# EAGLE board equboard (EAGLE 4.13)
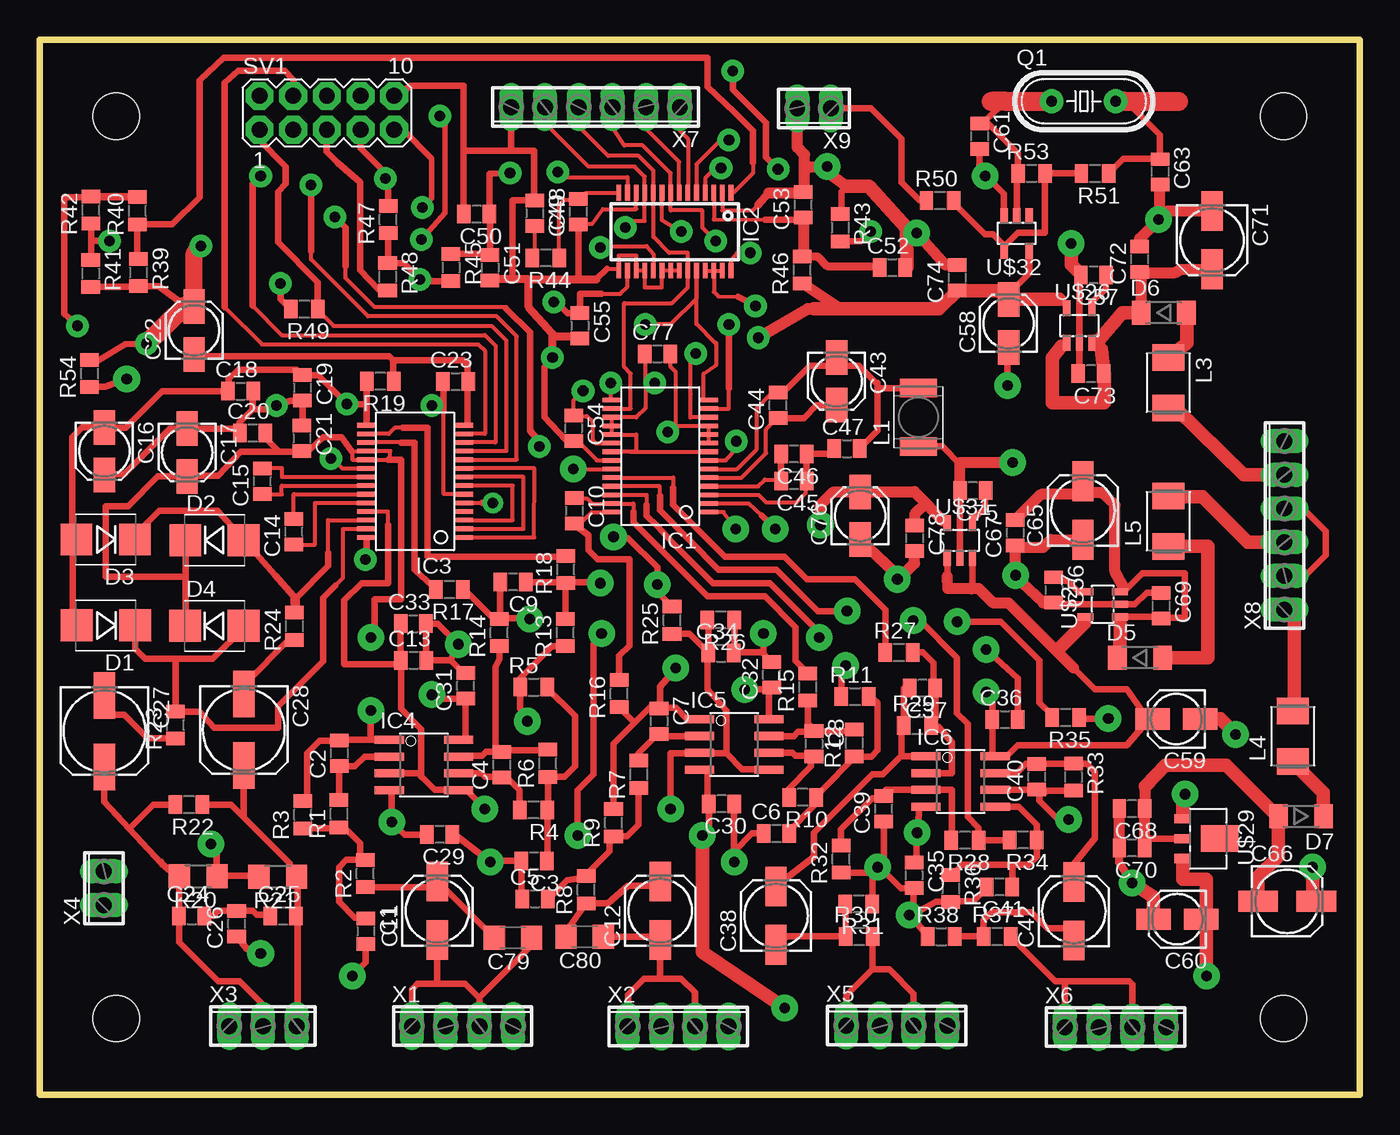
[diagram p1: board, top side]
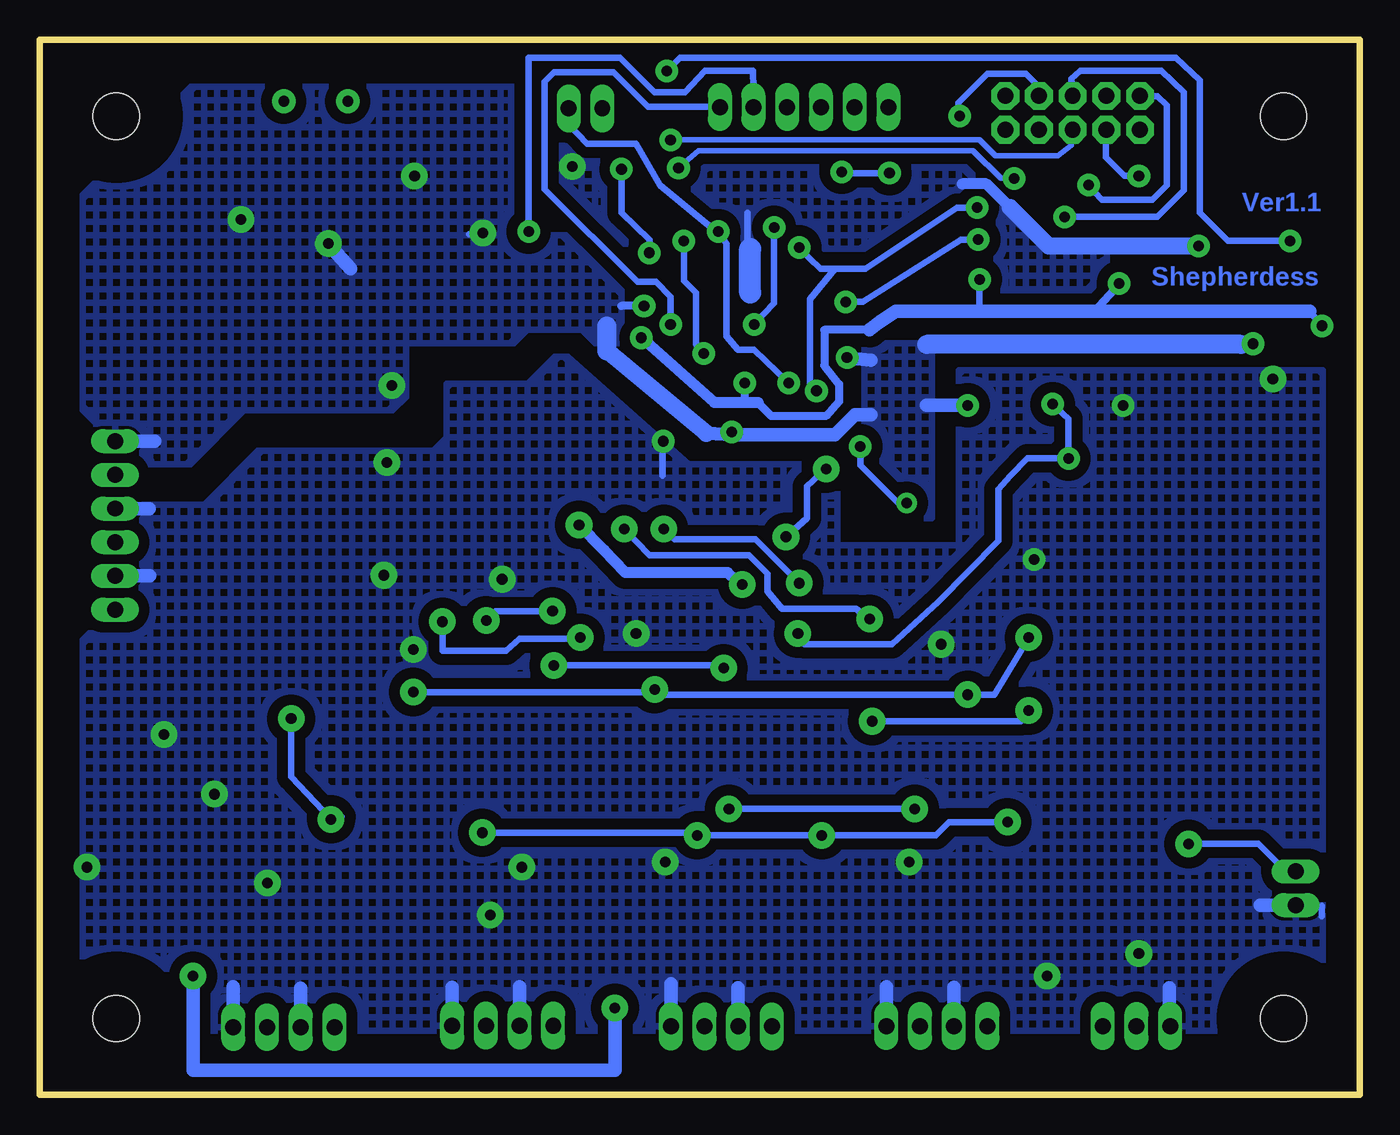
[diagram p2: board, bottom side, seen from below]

Size 99.5 x 79.5 mm. Coordinates in mm from the lower left corner, seen from the top.
Outline: 0,0 0,79.5 99.5,79.5 99.5,0 0,0
Copper layers (1*16): Top 0.035mm / dielectric 1.5mm / Bottom 0.035mm
Design rules "default": minimum track width 10mil, minimum drill 30mil, track to track 12mil, track to pad 12mil, pad to pad 10mil, via to via 10mil, smd to smd 8mil, copper to edge 20mil, drill to drill 20mil, minimum pad ring 10mil, minimum via ring 8mil, stop-mask expansion 4mil, vias tented up to drill 40mil, thermal gap 10mil
Net classes: 1 Phantom: drill 0.711 mm
Holes 3.5 mm at 93.75,5.75 5.75,5.75 5.75,73.75 93.75,73.75
bRestrict: area 3.4,3.4 to 8.1,8.1; area 91.5,3.5 to 96,8.1; area 91.5,71.5 to 96,76; area 3.5,71.5 to 8.1,76

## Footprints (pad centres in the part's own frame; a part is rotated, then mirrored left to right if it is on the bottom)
C0805 = smd 1.016 x 1.397: 1 -0.96,0; 2 0.96,0
153CLV-0505 = smd 3 x 1.6: + 2.2,0; - -2.2,0
153CLV-0405 = smd 2.6 x 1.6: + 1.8,0; - -1.8,0
153CLV-0605 = smd 3.5 x 1.6: + 2.7,0; - -2.7,0
C1206 = smd 1.6 x 1.8: 1 -1.4,0; 2 1.4,0
SMB = smd 2.4 x 2.4: 1 -2.2,0; 2 2.2,0
SOD80 = smd 1.4 x 1.8: 1 -1.7,0; 2 1.7,0
SSOP28DB = smd 0.348 x 1.397: 1 -4.225,-3.656; 2 -3.575,-3.656; 3 -2.925,-3.656; 4 -2.275,-3.656; 5 -1.625,-3.656; 6 -0.975,-3.656; 7 -0.325,-3.656; 8 0.325,-3.656; 9 0.975,-3.656; 10 1.625,-3.656; 11 2.275,-3.656; 12 2.925,-3.656; 13 3.575,-3.656; 14 4.225,-3.656; 15 4.225,3.656; 16 3.575,3.656; 17 2.925,3.656; 18 2.275,3.656; 19 1.625,3.656; 20 0.975,3.656; 21 0.325,3.656; 22 -0.325,3.656; 23 -0.975,3.656; 24 -1.625,3.656; 25 -2.275,3.656; 26 -2.925,3.656; 27 -3.575,3.656; 28 -4.225,3.656
PSO28 = smd 0.35 x 1.2: 1 -4.225,-2.925; 2 -3.575,-2.925; 3 -2.925,-2.925; 4 -2.275,-2.925; 5 -1.625,-2.925; 6 -0.975,-2.925; 7 -0.325,-2.925; 8 0.325,-2.925; 9 0.975,-2.925; 10 1.625,-2.925; 11 2.275,-2.925; 12 2.925,-2.925; 13 3.575,-2.925; 14 4.225,-2.925; 15 4.225,2.925; 16 3.575,2.925; 17 2.925,2.925; 18 2.275,2.925; 19 1.625,2.925; 20 0.975,2.925; 21 0.325,2.925; 22 -0.325,2.925; 23 -0.975,2.925; 24 -1.625,2.925; 25 -2.275,2.925; 26 -2.925,2.925; 27 -3.575,2.925; 28 -4.225,2.925
SO08 = smd 0.61 x 2.21: 1 -1.905,-2.616; 2 -0.635,-2.616; 3 0.635,-2.616; 4 1.905,-2.616; 5 1.905,2.616; 6 0.635,2.616; 7 -0.635,2.616; 8 -1.905,2.616
L5038P = smd 1.4 x 2.8: 1 -2.2,0; 2 2.2,0
L4532M = smd 2 x 2.4: 1 -1.9,0; 2 1.9,0
HC49/S = drill 0.8 pad 1.778 round: 1 -2.413,0; 2 2.413,0
R0805 = smd 1.016 x 1.397: 1 -1.023,0; 2 1.023,0
R1206 = smd 1.6 x 1.803: 1 -1.422,0; 2 1.422,0
MA05-2 = drill 1.2 pad 2.1 octagon: 1 -5.08,-1.27; 2 -5.08,1.27; 3 -2.54,-1.27; 4 -2.54,1.27; 5 0,-1.27; 6 0,1.27; 7 2.54,-1.27; 8 2.54,1.27; 9 5.08,-1.27; 10 5.08,1.27
SOT23-5 = smd 0.55 x 1.2: 1 -0.95,-1.3; 2 0,-1.3; 3 0.95,-1.3; 4 0.95,1.3; 5 -0.95,1.3
SOT89R = smd 0.7 x 1.1: 1 -1.5,-1.75; 2 0,-1.75; 3 1.5,-1.75 | smd 2 x 2.8: 4 0,1.1
4POL254 = drill 1.2 long: 1 -3.81,0; 2 -1.27,0; 3 1.27,0; 4 3.81,0
3POL254 = drill 1.2 long: 1 -2.54,0; 2 0,0; 3 2.54,0
2POL254 = drill 1.2 long: 1 -1.27,0; 2 1.27,0
6POL254 = drill 1.2 pad 1.778 long: 1 -6.35,0; 2 -3.81,0; 3 -1.27,0; 4 1.27,0; 5 3.81,0; 6 6.35,0

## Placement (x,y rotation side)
C1  1n  [C0805]  24.58,12.32 270 top
C2  220p  [C0805]  22.59,25.73 90 top
C3  1n  [C0805]  37.27,17.62 180 top
C4  220p  [C0805]  34.84,24.88 90 top
C5  1n  [C0805]  37.35,14.77 0 top
C6  1n  [C0805]  55.55,19.7 0 top
C7  220p  [C0805]  46.68,28.15 270 top
C8  220p  [C0805]  58.36,26.45 270 top
C9  220p  [C0805]  35.67,38.64 180 top
C10  220p  [C0805]  40.29,44.02 270 top
C11  47u 10V  [153CLV-0505]  29.97,13.87 90 top
C12  47u 10V  [153CLV-0505]  46.77,13.87 90 top
C13  100n (X7R)  [C0805]  28.18,32.74 0 top
C14  1u  [C0805]  19.16,42.43 90 top
C15  1u  [C0805]  16.78,46.23 90 top
C16  10u 6V  [153CLV-0405]  4.87,48.5 270 top
C17  10u 6V  [153CLV-0405]  11.11,48.4 270 top
C18  100n  [C0805]  15.13,53.02 0 top
C19  100n  [C0805]  19.8,53.27 270 top
C20  100n  [C0805]  16.03,49.88 0 top
C21  100n  [C0805]  19.76,49.47 270 top
C22  10u 6V  [153CLV-0405]  11.63,57.6 90 top
C23  100n  [C0805]  31.33,53.75 0 top
C24  1n  [C0805]  11.46,13.49 0 top
C25  1n  [C0805]  18.34,13.48 0 top
C26  1n  [C0805]  14.84,12.9 90 top
C27  33u 63V  [153CLV-0605]  4.88,27.4 270 top
C28  33u 63V  [153CLV-0605]  15.38,27.5 270 top
C29  10n  [C0805]  30.14,19.61 180 top
C30  10n  [C0805]  51.39,21.93 180 top
C31  10n  [C0805]  32.1,30.81 90 top
C32  10n  [C0805]  55.17,31.66 90 top
C33  2.2u  [C0805]  28.16,35.5 0 top
C34  2.2u  [C0805]  51.36,33.28 0 top
C35  100n  [C0805]  65.9,16.54 270 top
C36  100n  [C0805]  72.76,28.28 0 top
C37  33p  [C0805]  66.54,30.64 180 top
C38  47u 10V  [153CLV-0505]  55.5,13.5 90 top
C39  33p  [C0805]  63.62,21.56 90 top
C40  33p  [C0805]  75.16,23.96 90 top
C41  33p  [C0805]  72.34,15.66 180 top
C42  47u 10V  [153CLV-0505]  77.95,13.83 90 top
C43  15u  [153CLV-0405]  60.07,53.77 270 top
C44  100n  [C0805]  55.65,51.96 90 top
C45  100n  [C0805]  56.84,46.27 180 top
C46  1u  [C0805]  56.84,48.29 180 top
C47  100n  [C0805]  60.86,48.69 0 top
C48  68n  [C0805]  37.32,66.44 270 top
C49  1.5n  [C0805]  40.6,66.56 90 top
C50  100n  [C0805]  32.94,66.36 180 top
C51  2.2u  [C0805]  33.94,62.34 270 top
C52  2.2u  [C0805]  64.26,62.34 0 top
C53  100n  [C0805]  57.55,67.06 90 top
C54  10n  [C0805]  40.24,50.24 270 top
C55  10n  [C0805]  40.72,57.94 270 top
C56  10n (X7R)  [C0805]  76.44,38.04 270 top
C57  10n (X7R)  [C0805]  79.44,61.78 180 top
C58  15u (low ESR)  [153CLV-0405]  73.03,58.13 90 top
C59  10u (low ESR)  [153CLV-0405]  85.67,28.32 180 top
C60  10u (low ESR)  [153CLV-0405]  85.76,13.23 180 top
C61  18p  [C0805]  70.84,72.24 270 top
C63  18p  [C0805]  84.44,69.54 270 top
C65  22u 16V  [153CLV-0505]  78.63,44.03 90 top
C66  22u 16V  [153CLV-0505]  94.03,14.58 0 top
C67  1u  [C0805]  73.54,42.36 90 top
C68  1u  [C0805]  82.34,21.56 180 top
C69  100n (X7R)  [C0805]  84.52,36.84 270 top
C70  100n (X7R)  [C0805]  82.34,18.6 180 top
C71  22u 16V  [153CLV-0505]  88.37,64.4 270 top
C72  1u  [C0805]  82.92,62.96 90 top
C73  100n  [C0805]  79.24,54.34 180 top
C74  100n  [C0805]  69.16,61.56 90 top
C75  10n (X7R)  [C0805]  70.34,45.52 180 top
C76  10u (low ESR)  [153CLV-0405]  61.84,43.63 90 top
C77  100n  [C0805]  46.56,55.84 0 top
C78  100n  [C0805]  65.94,41.94 270 top
C79  4.7u  [C1206]  35.67,11.83 180 top
C80  4.7u  [C1206]  41.07,11.92 180 top
D1  [SMB]  4.98,35.38 180 top
D2  [SMB]  13.18,41.79 0 top
D3  [SMB]  4.97,41.85 180 top
D4  MBRA120LT3  [SMB]  13.17,35.34 0 top
D5  BAT42  [SOD80]  82.93,32.94 0 top
D6  BAT42  [SOD80]  84.73,58.92 0 top
D7  BAT42  [SOD80]  95.07,21 180 top
IC1  TLC320AD77  [SSOP28DB]  46.77,48.13 90 top
IC2  TAS3001  [PSO28]  47.88,65.04 180 top
IC3  PGA2500  [SSOP28DB]  28.29,46.23 90 top
IC4  OPA2134U  [SO08]  28.96,24.85 270 top
IC5  OPA2134U  [SO08]  52.35,26.4 270 top
IC6  OPA2134U  [SO08]  69.41,23.61 270 top
L1  33 uH  [L5038P]  66.23,51.06 90 top
L3  22uH 185mA  [L4532M]  85.07,53.67 270 top
L4  22uH 185mA  [L4532M]  94.45,27.03 90 top
L5  22uH 185mA  [L4532M]  85.07,43.23 90 top
Q1  24.576 MHz  [HC49/S]  78.7,74.87 0 top
R1  12k  [R0805]  22.56,21.18 90 top
R2  5.6k  [R0805]  24.53,16.68 90 top
R3  5.6k  [R0805]  19.82,21.1 90 top
R4  12k  [R0805]  37.22,21.46 180 top
R5  5.6k  [R0805]  37.23,30.72 0 top
R6  5.6k  [R0805]  38.3,24.98 90 top
R7  12k  [R0805]  45.16,24.15 90 top
R8  5.6k  [R0805]  41.18,15.45 90 top
R9  5.6k  [R0805]  43.25,20.5 90 top
R10  12k  [R0805]  57.5,22.42 180 top
R11  5.6k  [R0805]  61.45,30.01 0 top
R12  5.6k  [R0805]  61.41,26.5 90 top
R13  1k  [R0805]  39.61,34.83 90 top
R14  1k  [R0805]  34.63,34.83 90 top
R15  1k  [R0805]  57.9,30.73 90 top
R16  1k  [R0805]  43.67,30.23 90 top
R17  1k  [R0805]  30.88,38.07 180 top
R18  1k  [R0805]  39.65,39.58 90 top
R19  10  [R0805]  25.67,53.77 180 top
R20  6.81k  [R1206]  11.94,16.47 180 top
R21  6.81k  [R1206]  17.94,16.44 180 top
R22  620  [R0805]  11.24,21.86 180 top
R23  0 - 100  [R0805]  10.23,27.86 90 top
R24  0 - 100  [R0805]  19.2,35.31 90 top
R25  4.7k  [R0805]  47.66,35.76 90 top
R26  4.7k  [R0805]  51.34,35.78 180 top
R27  10k  [R0805]  64.76,33.34 0 top
R28  10k  [R0805]  69.74,19.18 180 top
R29  10k  [R0805]  66.16,27.84 0 top
R30  220  [R0805]  61.76,11.94 0 top
R31  100k  [R0805]  61.74,14.38 180 top
R32  100k  [R0805]  60.4,17.76 90 top
R33  10k  [R0805]  77.92,23.94 270 top
R34  10k  [R0805]  74.14,19.2 180 top
R35  10k  [R0805]  77.34,28.42 180 top
R36  100k  [R0805]  68.66,15.54 270 top
R37  220  [R0805]  72.16,11.94 0 top
R38  100k  [R0805]  67.96,11.92 0 top
R39  0  [R0805]  7.44,61.96 270 top
R40  inf  [R0805]  7.36,66.62 90 top
R41  0  [R0805]  3.84,61.9 270 top
R42  inf  [R0805]  3.86,66.68 90 top
R43  100k  [R0805]  60.34,65.34 270 top
R44  27  [R0805]  38.14,63.06 180 top
R45  2.7  [R0805]  31,62.34 270 top
R46  2.7  [R0805]  57.47,62.16 90 top
R47  5k(1board)  [R0805]  26.26,65.96 90 top
R48  5k(1board)  [R0805]  26.22,61.64 270 top
R49  10k  [R0805]  19.94,59.2 180 top
R50  100  [R0805]  67.86,67.4 0 top
R51  240  [R0805]  79.54,69.42 180 top
R53  750k  [R0805]  74.76,69.44 0 top
R54  10  [R0805]  3.76,54.36 90 top
SV1  [MA05-2]  21.64,74 0 top
U$26  LP2985IM5-3.3  [SOT23-5]  78.36,57.97 0 top
U$27  LP2985IM5-5.0  [SOT23-5]  80.13,36.96 90 top
U$29  79L05  [SOT89R]  87.83,19.3 270 top
U$31  LP2985IM5-3.3  [SOT23-5]  69.36,41.77 0 top
U$32  SN74AHC1G14  [SOT23-5]  73.64,64.92 180 top
X1  [4POL254]  31.87,5.17 0 top
X2  [4POL254]  48.12,5.15 0 top
X3  [3POL254]  16.83,5.17 0 top
X4  [2POL254]  4.83,15.56 90 top
X5  [4POL254]  64.6,5.21 0 top
X6  [4POL254]  81.1,5.09 0 top
X7  [6POL254]  41.89,74.43 180 top
X8  [6POL254]  93.83,42.91 90 top
X9  [2POL254]  58.37,74.33 180 top

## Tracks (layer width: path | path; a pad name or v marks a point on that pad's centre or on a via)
+3V3  (via drill 0.8 pad 2)
  Top 0.305: IC1.23 40.74,47.16 v40.23,47.17
  Top 0.508: R25.2 46.75,37.69 v46.55,38.45 46.55,39.75 44.35,41.95 v43.25,42.05 | U$31.5 68.41,43.09 68.25,43.15 68.05,43.25 | v58.85,42.95 58.85,43.05 | C76.+ 61.84,45.36 61.85,45.35 61.85,45.45
  Top 0.813: 66.78,44.58 65.95,45.45 61.85,45.45 | 66.78,44.58 68.05,43.25 | 66.78,44.58 65.94,43.74 C78.1 | C76.+ 59.83,45.43 58.85,44.45 58.85,43.05
  Bottom 0.508: v58.85,42.95 58.37,42.57 | v40.23,47.17 41.65,45.85 41.65,43.45 v43.25,42.05
  Bottom 0.813: v46.55,38.45 47.65,39.35 55.35,39.35 56.95,41.05 v58.85,42.95
+5V  (via drill 0.8 pad 2)
  Top 0.305: 26.25,47.85 IC3.19 23.55,47.85 23.55,48.51 | 23.5,48.51 23.55,48.51 | 23.55,48.51 IC3.18 | C21.2 19.76,48.54 19.75,48.55 20.25,48.55 | 24.88,48.51 26.42,48.51 26.42,47.84
  Top 0.508: D4.1 10.99,36.24 11,36.25 10.98,36.37 10.98,39.05 | 10.98,39.05 D2.1 | 31.25,26.75 IC4.8 31.55,26.75 32.15,26.75 32.1,26.8 C31.1 29.85,29.85 v29.55,30.15 | v53.15,30.55 54.95,30.55 55.15,30.75 | 55.15,30.75 55.17,30.73 C32.1 | IC5.8 54.97,30.57 55.15,30.75 | v71.35,30.35 71.8,30.3 C36.1 71.8,25.6 71.75,25.55 71.78,25.52 IC6.8 72.92,25.52 73.75,26.35 81.95,26.35 83.27,27.87 C59.+ 83.38,28.52 81.95,30.55 79.55,30.55 77.95,32.15 | v24.95,34.45 25.25,35.05 25.25,37.35 27.25,37.35 27.25,47.85 26.25,47.85 26.25,47.84 26.42,47.84 | 23.5,48.51 22.75,49.55 21.35,49.55 20.25,48.55 | 19.75,48.55 19.65,48.55 19.45,48.45 18.05,48.45 | 18.05,48.45 15.15,48.45 13.45,46.65 11.15,46.65 C17.+ 8.9,46.6 6.65,44.35 4.97,44.35 4.97,39.05 10.98,39.05 | C20.2 16.99,49.51 18.05,48.45 | U$27.5 78.79,36.05 78.75,36.05 78.75,35.55 | 76.65,33.45 76.85,33.65 | U$31.3 70.32,40.15 70.32,40.17 70.32,40.05 | 68.41,39.04 U$31.1 | 70.32,40.05 70.28,40.05 | 70.31,38.15 70.31,40.05 70.32,40.05
  Top 0.813: 77.95,32.15 76.65,33.45 73.05,37.05 71.89,37.05 70.79,38.15 70.15,38.15 | 68.41,39.04 68.44,38.15 70.15,38.15 | 70.15,38.15 70.31,38.15
  Top 1: 76.85,33.65 78.75,35.55
  Bottom 0.508: v71.35,30.35 53.35,30.35 v53.15,30.55 52.35,30.15 v29.55,30.15 27.55,30.15 v24.95,34.45
-5V  (via drill 0.8 pad 1.7, 0.8 pad 2)
  Top 0.305: IC3.20 22.8,47.2 22.05,47.95 v21.95,47.95 | IC3.15 24.65,50.45 24.65,50.75
  Top 0.508: 2.47,36.03 2.38,36.12 D1.2 | 2.47,36.03 2.47,41.75 | 2.47,41.75 D3.2 | 2.47,36.03 2.5,36 | IC4.4 26.45,22.95 26.52,22.88 26.52,20.58 v26.55,20.55 27.49,19.61 C29.2 | v40.55,19.55 40.55,22.95 41.75,24.15 41.75,33.95 v42.35,34.75 | IC5.4 49.79,24.55 50.35,24.55 50.35,21.95 50.41,21.95 C30.2 50.43,20.03 v49.95,19.55 | IC6.4 66.31,21.7 v66.15,19.75 66.1,19.4 66.1,18 66.15,17.95 C35.1 | U$29.3 86.08,17.82 86.15,17.35 | 24.65,52.05 v23.15,52.05 20.97,54.23 C19.1 19.38,54.65 14.95,54.65 14.25,53.95 14.25,52.95 C18.1 9.22,53.02 6.47,50.27 | 24.65,52.05 24.65,50.75 | R19.2 24.65,52.05 | 6.47,50.27 4.75,50.15 | 6.47,50.27 C16.- 3.2,50.3 2.45,49.55 2.45,41.75 2.47,41.75
  Top 1: v49.95,19.55 49.95,10.75 v56.15,6.55 | C60.- 87.56,13.56 87.55,13.55 87.75,13.35 | v87.95,8.95 87.95,13.15 87.75,13.35 | 86.15,17.35 86.15,16.25 87.95,16.25 87.95,13.55 87.75,13.35
  Bottom 0.508: v26.55,20.55 30.95,20.55 31.95,19.55 v40.55,19.55 v49.95,19.55 50.75,19.75 v66.15,19.75 | v42.35,34.75 41.85,33.95 35.25,33.95 31.75,37.15 27.25,41.75 27.25,45.65 26.35,46.65 25.05,47.95 v21.95,47.95 21.95,50.95 v23.15,52.05 23.15,52.15 23.25,52.05
  Bottom 1: v56.15,6.55 56.15,1.85 87.95,1.85 v87.95,8.95
AGND  (via drill 0.8 pad 1.7, 0.8 pad 2)
  Top 0.305: 24.6,42.01 IC3.28 24.65,41.8 | IC1.7 51.7,47.8 52.5,48.65 v52.5,49.25
  Top 0.406: 14.25,5.25 14.29,5.21 X3.1
  Top 0.508: C1.2 24.58,9.98 v23.55,8.95 | C29.1 31.29,19.61 v33.95,17.55 33.88,17.62 C3.2 36.31,14.59 36.35,14.55 36.39,14.59 C5.1 | 31.95,31.75 31.97,31.77 C31.2 | C13.2 30.96,32.74 31.95,31.75 | 31.95,31.75 30.95,32.75 v31.55,33.95 30,35.5 C33.2 29.12,32.78 C13.2 | C26.1 15.64,10.96 v16.65,10.65 | C30.1 52.35,18.55 52.25,18.44 | v52.35,17.55 52.25,18.44 | 52.25,18.44 52.26,18.44 52.35,18.35 53.7,19.7 C6.1 | C13.2 | C36.2 73.72,31.38 v71.35,33.55 | C70.2 81.38,18.58 81.35,18.55 | U$29.1 86.08,20.88 86.15,21.15 | C39.1 63.62,17.55 v63.15,17.15 | R32.1 63.16,16.74 | R31.1 62.76,16.36 v63.15,17.15 | 63.16,16.74 v63.15,17.15 | 63.16,16.74 63.16,16.96 63.35,17.15 64.92,15.58 C35.2 65.92,15.58 65.85,15.35 65.85,14.55 v65.55,13.55 | C41.2 71.38,15.58 70.38,14.58 68.78,14.58 68.72,14.72 R36.2 68.63,14.55 67.55,14.55 66.45,13.95 v65.55,13.55 | R38.1 66.94,11.96 65.85,13.25 v65.55,13.55 | v24.55,40.35 24.63,40.87 24.65,40.87 24.65,41.8 | 19.76,50.36 19.75,50.35 | 19.76,50.36 C21.1 | 19.76,50.36 19.8,50.4 C19.2 18.91,52.31 v17.85,51.95 17.55,51.65 16.05,51.65 | 16.05,51.65 15.07,50.67 C20.1 15.12,49.88 | C18.2 16.05,52.98 16.05,51.65 | 15.12,49.88 15.15,49.85 | 15.12,49.88 14.8,50.2 C17.- 9.8,50.2 6.35,46.75 4.85,46.75 4.87,46.73 C16.+ | 52.32,33.15 52.25,33.15 | C34.2 52.32,33.15 | 52.36,33.35 52.36,33.15 52.32,33.15 | 52.36,33.35 R26.1 | 52.36,33.35 52.25,33.35 | 54.44,33.35 C32.2 | 52.36,33.35 54.44,33.35 | 54.44,33.35 54.55,33.36 v54.55,34.75 | 64.85,38.95 v64.65,38.85 64.65,38.95 64.64,38.94 64.64,38.74 | C56.2 76.24,36.94 76.36,36.96 | 76.36,36.96 U$27.2 82.56,36.96 83.45,37.85 84.45,37.85 84.5,37.8 C69.1
  Top 0.508: 75.64,37.06 76.36,36.96 | v73.55,39.15 73.55,39.05 73.55,38.95 73.54,38.95 | 73.54,41.25 C67.1 | 73.54,38.94 73.45,38.85 | C75.2 69.38,45.78 69.35,45.75 69.36,45.74 U$31.2 | 69.38,47.45 69.45,47.45 68.04,48.86 L1.1 | X8.2 95.4,39.1 96.95,40.65 96.95,42.45 95.25,44.15 93.85,44.15 X8.4 | R54.1 4.94,53.34 v6.55,53.95
  Top 0.61: C70.2 81.38,17.52 v82.35,15.95
  Top 0.813: C70.2 C68.2 | 75.64,37.06 73.55,39.05 | 73.54,38.94 73.54,38.95 73.54,41.25 75.65,41.25 76.23,41.83 C65.- | C76.- 64.44,39.36 64.62,38.74 | 64.62,38.74 64.65,38.65 | C75.2 69.38,47.45 69.38,47.65 v73.35,47.65 | 64.62,38.74 64.64,38.74 65.94,40.04 C78.2
  Top 1: C60.+ 83.96,14.94 v82.35,15.95 | 86.15,21.15 86.15,21.95 86.35,22.45 v86.35,22.65 | C66.+ 95.95,15.1 v95.95,17.15 | C59.- 88.98,28.32 v90.15,27.15
  Bottom 0.508: 14.35,5.15 14.33,5.17 X3.1 | v33.95,17.55 33.75,17.55 | v64.65,38.85 64.65,38.95 64.75,38.95 | v52.5,49.25 52.55,49.25 52.55,46.65 | 2.85,13.45 2.85,14.25
  Bottom 1: 14.35,5.15 14.35,8.05 | 91.2,39.1 X8.2 | X6.4 84.91,8.15 | X6.2 79.83,8.03 | X5.4 68.41,8.09 | X5.2 63.33,5.33 63.35,5.45 63.35,8.15 | X2.4 51.93,8.35 | X2.2 46.85,8.05 | X1.2 30.6,8.1 | X1.4 35.68,8.15 | X4.1 7.51,14.29 | X8.4 93.85,44.16 93.85,44.15 91.25,44.15
  pour Bottom (isolate 0.813, hatched): 2.8,54.61 30.23,54.61 30.23,41.41 39.37,41.41 39.37,47.5 50.55,47.5 59.69,55.63 60.71,55.63 62.74,53.6 68.84,53.6 68.84,49.53 69.85,48.52 83.06,48.52 87.13,44.45 95.25,44.45 95.25,35.31 96.27,34.29 96.27,9.91 91.19,4.83 6.86,4.83 2.8,8.89
AUDMCLK  (via drill 0.8 pad 1.7)
  Top 0.305: IC2.9 46.91,65.91 v48.35,65.05 | IC1.15 43.05,52.42 v43.05,53.65
  Top 0.508: R50.1 66.3,67.4 64.95,68.75 64.95,72.05 62.65,74.35 60.05,74.35 59.97,74.43 | 59.97,74.43 59.95,74.45 | X9.1 59.97,74.43
  Bottom 0.305: 59.65,74.35 X9.1 59.65,74.35 | 59.65,74.35 59.75,74.35 | v48.35,65.05 48.85,65.35 | 59.65,73.15 59.65,74.35
  Bottom 0.508: v48.35,65.05 47.75,64.15 47.75,57.15 46.85,56.15 45.65,56.15 v43.05,53.65 | 48.85,65.35 52.75,68.55 54.55,71.65 58.25,71.65 59.65,73.15
GND  (via drill 0.8 pad 1.7, 0.8 pad 2)
  Top 0.305: IC3.6 30.45,45.26 30.45,51.55 | IC1.9 50.43,49.73 50.45,49.75 | IC1.22 41.99,47.8 40.45,49.35 40.25,49.35 C54.2 | 47.95,50.31 47.95,54.45 47.55,54.85 47.55,55.75 | IC2.12 44.95,66.75 42.45,66.75 41.65,65.65 40.55,65.65 | 40.55,65.65 | C49.1 40.55,65.65 | 43.66,62.25 IC2.15 | 43.66,62.25 43.66,63.25 44.95,63.25 IC2.17 44.95,62.15 | IC2.26 50.8,60.51 51.15,60.16 52.65,60.15 | 57.25,68.05 57.32,68.05 C53.2 57.55,67.97 | 42.75,62.25 43.66,62.25 | IC2.27 51.45,62.15 51.41,62.12 IC2.26 | 50.16,62.15 50.15,62.15 | IC2.25 50.16,62.15 | IC2.26 50.19,62.12 50.16,62.15 | 47.55,62.15 | IC2.22 48.2,62.15 47.55,62.15 | 47.55,62.15 IC2.21 | 47.55,62.15 46.91,62.15 IC2.20 46.91,60.85 45.6,60.85 IC2.18 45.6,62.15 44.95,62.15 | 44.95,62.15 | IC2.2 51.45,66.65 53.75,66.65 54.15,67.05 | 47.86,50.24 47.85,50.25 48.01,50.41 IC1.11 50.43,49.77 50.45,49.75 | 50.45,49.75 50.45,49.76 IC1.10
  Top 0.508: 30.45,52.05 30.45,53.45 30.37,53.53 C23.1 | 30.45,51.55 30.45,52.05 | 30.45,52.05 30.15,51.95 v29.55,51.95 | C73.2 78.26,54.34 78.25,54.35 78.36,54.46 U$26.2 78.36,61.56 78.48,61.68 C57.2 | 72.93,56.57 C58.- | v72.95,53.45 72.93,56.57 | 72.95,56.35 72.95,56.45 | 72.95,56.35 72.95,55.95 | 72.93,56.57 72.93,56.37 72.95,56.35 | 68.28,62.52 C74.2 | 47.55,55.75 47.52,55.78 C77.2 | 66.11,64.79 v66.11,64.94 65.35,65.34 | 52.65,60.15 v53.95,59.45 | C53.2 57.32,68.02 57.25,67.95 | 7.52,60.88 7.46,60.94 R39.2 8.96,60.94 10.95,59.45 | 7.52,60.88 R41.2 | 7.52,60.88 7.55,60.85 | 11.55,59.45 11.6,59.4 C22.+ 11.63,59.45 11.65,59.45 11.65,59.55 | 35.54,71.15 X7.6 | 35.54,71.15 37.25,71.15 37.25,67.55 37.35,67.45 37.32,67.42 C48.1 35.65,67.4 35.65,61.45 | C50.2 31.95,66.39 31.95,71.15 | 35.54,71.15 35.55,71.15 | 35.54,71.15 31.95,71.15 | 41.95,61.45 42.75,62.25 | 31.95,71.15 31.95,76.05 27.95,76.05 26.75,75.15 26.63,75.27 | 26.63,75.27 26.55,75.35 | 26.63,75.27 SV1.10 | 65.35,62.37 C52.2 | 34.15,61.45 34.15,61.38 C51.2 | 40.52,56.98 40.65,56.95 | 40.52,56.98 C55.2 | 40.35,57.15 40.52,56.98 | C49.1 40.6,61.5 40.55,61.45 | 40.25,49.35 39.65,49.35 38.05,51.05 38.05,54.85 v38.65,55.55 | 38.65,57.15 38.65,57.35 | 47.95,50.31 47.86,50.24 47.49,49.95 v47.35,49.95 | 60.44,66.36 60.45,66.35 | 60.44,66.36 R43.1 | 57.55,67.97 57.65,67.95 | 57.65,69.55 57.69,69.95 | 4.46,55.36 4.45,55.35 | R54.2 4.46,55.36 | v8.05,56.6 6.45,56.55 4.46,55.36 | 60.81,68.45 60.81,68.41 60.44,68.03 60.44,66.36 | C61.2 70.84,69.66 v71.25,69.25 71.25,69.35 72.69,67.91 U$32.3
  Top 0.61: 54.15,67.05 54.95,67.97 | 36.85,61.45 35.65,61.45 34.15,61.45 | 36.85,61.45 40.55,61.45 41.95,61.45 | 38.65,57.35 36.85,59.35 36.85,61.45 | v38.65,55.55 38.65,57.15 40.35,57.15 | 57.69,69.85 57.69,69.95 57.65,69.95 | v59.35,69.95 59.35,69.55
  Top 0.813: v66.11,64.94 68.28,62.52 | 54.95,67.97 57.55,67.97 | X9.2 57.1,71.4 57.65,70.85 57.65,69.95 57.65,69.55 57.65,67.95 | 59.35,69.55 60.81,68.45 | 57.69,69.95 v59.35,69.95 | C72.2 82.92,64.52 v84.35,65.95 | v84.35,65.95 84.45,65.95 84.44,65.96 C63.2 | C71.- 85,66.6 v84.35,65.95
  Top 1: C57.2 78.48,61.82 77.75,62.55 v77.75,64.15
  Top 1.016: 65.35,62.37 65.35,65.34 62.5,68.45 60.81,68.45
  Top 1.27: 10.95,59.45 11.55,59.45 | v8.05,56.6 8.05,56.65 | 11.65,59.55 11.65,63.45 v12.15,63.95
  Top 1.422: 8.05,56.65 10.95,59.45
  Bottom 0.508: 47.26,49.92 v47.35,49.95 | 47.26,49.92 47.05,49.85 | v66.11,64.94 65.85,64.81 67.15,64.85 | v8.05,56.6 8.95,56.55 | 47.25,49.75 47.25,49.93 47.26,49.92 | 45.95,60.45 arc90 46.15,60.65 46.15,66.45
  Bottom 0.61: v53.95,59.45 55.65,59.45
  Bottom 0.813: 29.95,68.65 28.15,68.65 26.35,66.85
  Bottom 1: 90.84,49.26 X8.6 | v77.75,64.15 76.05,62.25
  Bottom 1.016: 49.25,49.85 47.25,49.75 39.55,49.75 38.05,51.25 36.85,51.25 | v38.65,55.55 36.85,55.35 | v29.55,51.95 32.65,51.95
  Bottom 1.27: 49.25,49.85 56.75,56.05 | v12.15,63.95 23.45,63.95 26.35,66.85
  Bottom 1.422: 56.75,56.05 56.75,57.95 | 8.95,56.55 32.65,56.55
  Bottom 1.676: 45.95,60.45 45.95,63.75
  pour Bottom (isolate 0.813, hatched): 95.25,47.5 95.25,50.55 96.27,51.57 96.27,67.82 88.14,75.95 63.76,75.95 63.76,65.79 62.74,64.77 59.69,64.77 55.63,60.71 55.63,56.65 57.66,56.65 58.68,57.66 62.74,57.66 63.76,56.65 71.89,56.65 71.89,52.58 72.9,51.57 84.08,51.57 88.14,47.5
  pour Bottom (isolate 0.813, hatched): 61.45,71.65 61.45,68.25 54.45,61.25 51.75,61.25 51.75,62.55 55.65,66.45 55.65,71.65 58.25,71.65 59.45,72.85 61.45,72.85 61.45,71.85
  pour Bottom (isolate 0.813, hatched): 29.21,66.81 29.21,70.87 50.55,70.87 50.55,66.81 47.5,63.76 42.42,63.76 34.29,63.76 31.25,66.81
  pour Bottom (isolate 0.813, hatched): 32.26,56.65 32.26,43.44 37.34,43.44 37.34,56.65
  pour Bottom (isolate 0.813, hatched): 19.05,63.76 19.05,59.69 28.2,59.69 28.2,67.82 23.12,63.76
MIC0DB
  Top 0.305: IC3.2 | IC3.8 36.45,46.55 36.45,42.65 IC3.2
MICDCEN
  Top 0.305: IC3.7 35.65,45.91 35.65,43.31 IC3.3
MICZCEN
  Top 0.305: IC3.1 31.96,42.02 IC3.1 | IC3.9 37.28,47.2 37.26,42.01 IC3.1
N$1
  Bottom 0.5: 0,0 0,79.5 99.5,79.5 99.5,0 0,0
N$2
  Top 0.5: 0,0 0,79.5 99.5,79.5 99.5,0 0,0
N$3
  Top 0.508: R3.1 22.48,20.08 R1.1 22.94,20.16 24.15,18.95 24.15,17.95 24.53,17.57 | 24.53,17.57 24.55,17.55 | 24.53,17.57 R2.2 23.1,17.7 22.55,17.15 22.55,14.55 23.75,13.35 24.55,13.35 24.58,13.32 C1.1
N$4
  Top 0.508: IC4.2 24.48,25.48 23.75,24.75 22.55,24.75 | 22.55,24.75 22.57,24.77 C2.1 | R1.2 22.56,24.74 22.55,24.75
N$5  (via drill 0.8 pad 2)
  Top 0.508: 24.95,26.75 22.55,26.75 22.59,26.71 C2.2 21.09,26.69 20.15,25.75 20.15,22.55 19.75,22.15 19.78,22.12 R3.2 | 24.95,26.75 IC4.1 | v36.75,28.15 36.21,29.09 R5.1 36.21,31.41 38.61,33.81 R13.1 | 24.95,26.75 | 24.95,26.75 v24.95,28.95
  Bottom 0.508: v36.75,28.15 25.55,28.15 v24.95,28.95
N$6
  Top 0.508: R6.1 | R6.1 39.55,23.95 40.35,24.75 40.35,28.55 38.18,30.72 | 38.26,21.46 R4.1 | R6.1 38.31,22.11 38.26,21.46 | C3.1 38.15,17.55 | C3.1 | 38.26,21.46 38.26,17.66 C3.1 | 38.18,30.72 38.15,30.75 | 38.18,30.72 R5.2
N$7
  Top 0.508: 34.92,23.92 34.95,23.95 33.55,23.95 33.28,24.21 IC4.6 | 34.92,23.92 C4.1 | 34.92,23.92 35.18,23.92 36.15,22.95 36.15,21.55 36.2,21.5 R4.2
N$8  (via drill 0.8 pad 2)
  Top 0.305: IC1.1 51.55,43.91 v52.45,42.65
  Top 0.508: R13.2 39.65,35.85 R18.1 39.74,38.64 | C9.1 39.74,38.64 | 39.74,38.64 39.75,38.65 | 39.74,38.64 41.64,38.64 v42.25,38.55
  Bottom 0.508: v52.45,42.65 51.65,41.85 45.55,41.85 v42.25,38.55
N$9
  Top 0.508: C5.2 38.31,14.71 39.75,16.15 40.95,16.35 40.98,16.32 R8.2 40.98,16.38 42.95,18.35 42.95,19.15 43.28,19.48 | 43.28,19.48 43.35,19.55 | 43.28,19.48 R9.1 44.28,19.48 45.15,20.35 45.15,23.15 R7.1
N$10
  Top 0.305: IC1.24 47.75,46.51 47.75,45.75
  Top 0.508: 47.75,45.75 47.75,44.45 51.65,40.55 56.15,40.55 57.85,38.85 61.45,38.85 63.75,36.55 R27.1
N$11
  Top 0.508: 46.68,27.22 46.55,27.35 | 46.68,27.22 C7.2 46.59,27.19 45.15,25.75 45.15,25.15 R7.2 | IC5.2 46.87,27.04 46.68,27.22
N$12  (via drill 0.8 pad 2)
  Top 0.508: R9.2 43.25,26.45 44.85,28.05 | 44.85,28.05 45.95,29.15 46.55,29.15 46.59,29.11 | 46.59,29.11 C7.1 | IC5.1 48.8,28.3 47.95,29.15 46.75,29.15 | 46.59,28.99 46.55,28.95 | 46.59,29.11 46.59,28.99 | 46.59,28.99 46.75,29.15 | R11.1 60.43,32.03 v60.75,32.35 | v47.95,32.15 46.75,30.75 46.75,29.15 | 44.85,28.05 44.75,28.15 44.73,28.15 R16.1
  Bottom 0.508: v60.75,32.35 48.75,32.35 48.35,31.95 v47.95,32.15
N$13
  Top 0.508: R11.2 62.61,30.01 63.15,29.55 63.15,25.95 62.68,25.48 R12.1 61.02,25.48 61.35,25.35 58.92,22.92 R10.1 58.52,21.92 56.35,19.75 56.4,19.7 C6.2
N$14  (via drill 0.8 pad 2)
  Top 0.305: IC1.2 52.45,44.55 53.45,44.55 54.45,43.65
  Top 0.508: R17.1 32.03,38.07 34.25,35.85 R14.2 34.65,35.85 34.7,35.9 | 34.7,35.9 34.71,35.91 36.81,35.91 v36.95,35.85 | 34.7,35.9 34.71,35.89 | 34.71,35.89 C9.2 | 34.71,35.89 34.75,35.85 | v55.45,42.65 54.45,43.65
  Bottom 0.508: v55.45,42.65 53.55,40.65 46.05,40.65 44.65,39.25 44.65,37.95 43.54,36.61 37.99,36.62 v36.95,35.85
N$15
  Top 0.508: IC5.6 56.73,25.77 56.95,25.55 58.35,25.55 | R10.2 56.48,23.08 58.15,24.75 58.15,25.35 58.35,25.55 | 58.35,25.55 58.36,25.54 C8.2
N$16
  Top 0.508: R6.2 38.35,25.95 34.95,25.95 C4.2 | C4.2 34.35,26.33 34.35,32.25 34.65,32.85 34.65,33.93 | 34.65,33.93 34.45,33.85 | 34.65,33.93 R14.1 | C4.2 33.64,25.84 33.35,25.55 31.55,25.55 31.58,25.52 IC4.7
N$17
  Top 0.508: IC5.7 56.84,27.04 57.15,27.35 58.35,27.35 58.36,27.36 C8.1 | 61.52,27.52 61.55,27.55 | 61.52,27.52 R12.2 | C8.1 61.41,27.41 61.52,27.52 | C8.1 58.36,27.54 57.9,28 R15.1
N$18
  Top 0.305: 44.75,43.95 44.75,44.55 IC1.27 41.65,44.55 41.25,44.95 40.35,44.95 40.32,44.98 C10.1
  Top 0.508: R15.2 56.95,32.7 56.95,35.25 54.65,37.55 50.35,37.55 44.75,43.15 44.75,43.95
N$19
  Top 0.305: 40.51,42.8 40.51,42.81 41.6,43.91 IC1.28
  Top 0.508: R16.2 43.67,33.07 44.45,33.85 44.45,40.35 42.05,40.35 41.35,41.05 41.35,42.15 40.51,42.8 40.45,42.85 40.36,43.06 C10.2
N$20
  Top 0.508: R2.1 29.26,15.66 29.95,16.35 29.97,16.33 C11.+ 30.03,16.07 34.15,11.95 34.07,11.87 C79.2
N$21
  Top 0.508: 46.87,16.07 46.95,16.15 | 46.87,16.07 C12.+ | 46.87,16.07 46.75,15.75 44.35,15.75 42.83,14.43 R8.1 40.98,14.18 39.67,12.27 C80.2
N$22
  Top 0.305: IC3.16 26.3,49.8 26.75,50.25 27.35,50.25
  Top 0.508: 27.35,50.25 29.25,50.25 29.25,40.55 39.65,40.55 R18.2
N$23
  Top 0.305: IC3.17 27.25,49.16 27.25,49.15
  Top 0.508: R17.2 29.56,38.35 28.25,39.55 28.25,49.15 27.25,49.15
N$24
  Top 0.508: 33.25,5 33.14,5.11 X1.3 33.15,5.15 33.15,7.25 33.1,7.3 | 33.1,7.3 32.05,8.35 29.95,8.35 | 28.35,8.25 28.37,8.25 | 29.95,8.35 28.45,8.35 28.35,8.25 | X1.1 28.06,7.96 28.35,8.25 | C11.- 29.95,11.67 29.95,8.35 | C79.1 36.87,11.07 33.1,7.3
N$25
  Top 0.508: X2.1 44.35,5.15 44.35,7.55 45.55,8.75 46.75,8.75 | X2.3 49.39,7.71 48.35,8.75 46.75,8.75 | C80.1 45.98,11.92 46.17,11.73 C12.- 46.77,8.77 46.75,8.75
N$26
  Top 0.305: IC3.24 20.75,44.6 20.75,41.45 19.05,41.45 C14.1
N$27
  Top 0.305: IC3.22 18.25,45.91 18.25,45.25 16.75,45.25 16.75,45.27 C15.1
N$28
  Top 0.305: C14.2 19.05,43.35 | C14.2 | IC3.23 19.15,45.26 C14.2
N$29
  Top 0.305: IC3.21 18.25,46.55 18.25,47.25 16.85,47.25 16.85,47.19 | 16.85,47.19 16.85,47.15 | C15.2 16.85,47.19
N$30
  Top 0.305: 32.25,50.45 | 32.25,50.45 IC3.14 | 32.25,50.65 32.25,50.45
  Top 0.508: 32.25,53.75 C23.2 | 32.25,53.75 32.25,50.65 | 32.25,53.75 32.25,55.05 31.95,55.35 26.65,55.35 26.65,55.25 | 26.67,53.77 26.65,53.75 | 26.67,53.77 R19.1 | 26.65,55.25 26.67,53.77 | C22.- 11.8,55.6 12.05,55.65 26.35,55.65 26.75,55.25 26.65,55.25
N$31
  Top 0.508: U$27.4 78.29,37.91 77.45,38.75 76.35,38.75 76.3,38.8 C56.1
N$32
  Top 0.508: 15.38,22.25 15.38,22.18 | 15.38,22.25 15.35,22.25 15.35,20.95 15.45,20.85 | 15.45,20.85 18.85,17.45 18.85,16.35 19.15,16.35 19.25,16.45 19.26,16.44 R21.1 19.45,16.35 19.45,13.63 C25.2 19.33,13.45 19.45,13.45 19.45,5.25 X3.3 | C28.+ 15.35,24.77 15.35,22.28 15.38,22.25 | R22.1 14.44,21.86 15.45,20.85
N$33
  Top 0.508: C24.2 13.09,13.49 13.45,13.85 14.95,13.85 14.94,13.86 C26.2 16.04,13.86 16.35,13.55 17.25,13.55 17.35,13.45 C25.1
N$34
  Top 0.508: X3.2 16.83,6.27 16.75,6.35 16.75,6.85 15.05,8.55 13.45,8.55 10.5,11.5 C24.1 10.5,16.2 10.55,16.25 10.52,16.28 R20.2 10.33,16.47 9.2,17.4 | 9.2,17.4 9.15,17.55 | 4.85,24.85 4.88,24.82 C27.+ | 9.2,17.4 6.74,20.04 | 6.74,20.04 4.85,22.07 4.85,24.85 | 4.85,24.85 4.75,24.95 | 6.74,20.04 8.56,21.86 R22.2
N$35  (via drill 0.8 pad 2)
  Top 0.305: 26.25,42.95 26.25,43.95 IC3.25 | IC3.25 24.55,43.95 | IC3.25
  Top 0.508: IC4.3 28.54,24.21 28.77,23.98 | 28.77,23.98 29.75,23 31.25,23 31.3,22.95 IC4.5 32.16,22.95 v33.55,21.55 | v47.55,21.55 47.55,25.75 49.85,25.75 | 28.77,23.98 28.75,23.95 28.75,27.55 27.22,29.08 C13.1 27.16,32.74 27.15,32.75 27.2,32.8 C33.1 27.2,32.45 22.95,32.45 22.95,37.25 24.25,38.55 26.25,38.55 26.25,42.95 | 49.85,25.75 51.75,25.75 | 51.75,25.75 52.95,24.55 54.95,24.55 55.01,24.5 | 51.75,25.75 51.75,28.95 50.35,30.55 50.35,33.25 50.4,33.2 | 50.35,35.75 R26.2 50.4,35.7 C34.1 | C34.1 50.4,33.3 48.96,34.74 R25.1 | IC5.3 49.84,25.77 49.85,25.75 | 55.01,24.5 IC5.5 | 55.01,24.5 55.05,24.45 | 50.4,33.2 50.45,33.15 | 50.4,33.2 C34.1
  Bottom 0.508: v33.55,21.55 v47.55,21.55
N$36
  Top 0.508: 4.95,31.15 4.9,31.1 C27.- 4.85,30.07 4.85,29.25 5.45,28.65 6.35,28.65 8.15,26.85 10.22,26.85 R23.1
N$37
  Top 0.406: 19.25,34.25 19.21,34.29 R24.1
  Top 0.508: R24.1 19.15,34.35 18.85,34.35 15.45,30.95 15.45,30.25 15.4,30.2 C28.-
N$38
  Top 0.305: IC3.27 | 10.38,28.86 R23.2 | IC3.27 24.65,42.65 | IC3.27 22.85,42.65 22.85,38.95 22.25,38.35
  Top 0.508: 6.78,35.52 D1.1 7.18,33.62 7.95,32.85 10.25,32.85 | 15.35,35.35 15.34,35.34 D4.2 15.35,35.32 15.35,35.15 13.05,32.85 10.25,32.85 | 10.38,28.86 12.05,28.86 13.14,27.64 17.98,27.64 17.98,29.29 21.35,32.67 21.35,32.85 21.35,37.45 22.25,38.35 | R23.2 10.23,32.83 10.25,32.85
N$39
  Top 0.305: IC3.26 21.72,43.3 21.72,40.85 21.75,40.85 | R24.2
  Top 0.508: 15.45,41.75 17.75,39.15 19.15,37.55 19.17,36.33 R24.2 19.23,36.33 19.35,36.45 19.35,37.45 21.75,39.85 21.75,40.85 | D3.1 6.87,41.87 9,44 13.4,44 15.45,41.75 | 15.45,41.75 15.28,41.78 D2.2
N$40
  Top 0.305: IC3.11 35.15,48.51 35.15,56.85 34.05,57.95 22.15,57.95 20.9,59.2
  Top 0.508: 20.95,59.25 20.9,59.2 R49.1 20.96,61.24 17.95,64.25 17.95,68.05 18.55,68.65 18.55,69.95 16.55,71.95 16.55,72.75 SV1.1
N$41  (via drill 0.8 pad 2)
  Top 0.305: IC1.25 46.75,45.85 46.75,45.15
  Top 0.508: 70.76,19.16 70.75,19.15 | 70.76,19.16 R28.1 70.76,20.14 69.95,20.95 69.95,27.95 69.15,28.75 69.15,32.95 66.35,35.75 v65.85,35.75 | R34.2 70.8,19.2 70.76,19.16 | 46.75,45.15 46.75,44.05 51.15,39.55 55.55,39.55 58.65,36.45 v60.85,36.45
  Bottom 0.508: v60.85,36.45 65.15,36.45 v65.85,35.75
N$42
  Top 0.508: IC6.2 68.75,24.25 68.75,26.55 67.75,27.75 67.15,27.75 66.98,27.58 | 66.98,27.58 66.95,27.55 | 66.98,27.58 R29.2 | R29.2 66.95,27.64 | R29.2 67.18,27.92 67.15,27.95 67.5,28.3 C37.1 67.46,30.64 67.35,30.75 67.35,32.55 66.56,33.34 R27.2
N$43
  Top 0.508: 63.52,22.52 63.55,22.55 | 63.52,22.52 C39.2 | 63.35,22.35 63.52,22.52 | C39.2 63.38,22.52 63.35,22.55 63.78,22.98 IC6.3 68.75,22.98 68.75,19.18 | 68.75,19.18 68.75,19.15 | 68.75,19.18 R28.2 | R32.2 60.4,20 62.75,22.35 63.35,22.35 | 63.55,22.55 63.58,22.52 C39.2 | 63.35,22.35 63.55,22.55
N$44
  Top 0.508: 64.95,25.52 64.92,25.52 63.55,24.15 62.75,24.15 58.35,19.75 58.35,17.95 C38.+ | 64.95,25.52 IC6.1 | 64.95,25.52 64.95,27.64 R29.1 | R29.1 65.15,27.75 | C37.2 65.15,30.64 R29.1
N$45
  Top 0.508: C38.- 56.34,11.94 R30.1 60.75,14.18 R31.2
N$46
  Top 0.508: X5.1 60.79,7.49 62.75,9.45 | R30.2 62.76,11.94 62.75,11.95 62.75,9.45 | X5.3 65.87,7.63 64.05,9.45 62.75,9.45
N$47  (via drill 0.8 pad 2)
  Top 0.305: IC1.26 45.75,45.2 45.75,44.45
  Top 0.508: R35.2 76.32,28.58 75.35,29.55 75.35,32.75 72.45,35.65 v69.15,35.65 | 45.75,44.45 45.75,43.65 46.55,42.85 47.75,41.55 50.75,38.55 55.05,38.55 58.85,34.75 v58.75,34.45
  Bottom 0.508: v58.75,34.45 58.85,34.35 63.35,34.35 64.35,33.45 69.15,33.45 v69.15,35.65
N$48
  Top 0.508: IC6.5 73.8,21.7 75.15,20.35 75.15,19.35 | 75.15,19.15 75.16,19.16 R34.1 | 75.15,19.15 75.15,19.35 | R36.1 68.76,16.56 69.55,17.35 73.35,17.35 | 73.35,17.35 74.55,17.35 75.15,17.95 75.15,19.15 | 75.15,19.35 75.35,19.35 75.15,19.15 | C41.1 73.3,17.3 73.35,17.35
N$49  (via drill 0.8 pad 2)
  Top 0.508: C40.1 75.76,22.76 75.55,22.95 75.38,22.92 R33.2 | C40.1 75.16,23.14 75.15,23.15 74.97,22.98 IC6.6 | R35.1 78.36,28.34 80.16,28.34 v80.55,28.35 | v77.55,20.75 76.75,20.75 75.35,22.15 75.35,22.75 75.15,22.95 75.16,22.96 C40.1
  Bottom 0.508: 76.75,20.95 v77.55,20.75 80.55,23.95 v80.55,28.35
N$50
  Top 0.305: IC1.5 52.91,46.51 54.75,48.35 54.75,50.15 55.65,51.05 C44.1
  Top 0.508: C44.1 57.6,51 58.55,51.95 59.95,51.95 60.05,51.85 60.07,51.87 C43.+
N$51
  Top 0.508: C42.+ 77.75,17.15 79.55,19.35 79.55,24.35 78.95,24.95 77.95,24.95 77.94,24.96 R33.1 75.16,24.96 75.15,24.95 75.16,24.94 C40.2 74.98,24.92 74.95,24.95 74.35,24.95 73.64,24.25 IC6.7
N$52
  Top 0.508: C42.- 77.95,12.55 75.95,12.55 74.75,13.75 71.75,13.75 71.15,13.15 R37.1 68.96,11.94 | 68.96,11.94 R38.2 | 68.96,11.94 68.95,11.95
N$53
  Top 0.508: X6.1 77.29,8.49 77.35,8.55 | X6.3 82.37,8.33 82.15,8.55 77.35,8.55 | 73.16,11.94 73.15,11.95 | 73.16,11.94 R37.2 | 77.35,8.55 76.55,8.55 73.16,11.94
N$54
  Top 0.305: IC1.6 52.55,47.16 54.05,48.65 54.05,51.75 55.15,52.85 55.18,52.92 C44.2
  Top 0.508: C44.2 56.02,52.92 58.05,54.95 59.65,54.95 60.15,55.45 60.07,55.53 C43.- 60.07,55.33 60.45,54.95 61.75,54.95 63.05,53.65 63.15,53.65 63.15,53.55 | C47.2 61.82,48.72 63.15,50.05 63.15,53.55 | L1.2 63.16,53.26 63.15,53.55
N$55
  Top 0.305: IC1.4 54.16,45.85 54.65,46.35 55.85,46.35 55.85,46.27 C45.2
  Top 0.508: C46.2 55.88,48.08 55.85,48.05 55.88,48.02 C45.2
N$56
  Top 0.305: IC2.1 52.15,68.02 52.25,67.95 53.75,69.45 53.75,70.25
  Top 0.508: R39.1 7.44,63.14 7.45,63.15 7.36,63.24 R40.1 10,65.6 12.05,67.65 12.05,76.45 13.85,78.15 50.35,78.15 50.35,75.95 52.35,74.05 53.75,72.65 53.75,70.25
N$57
  Top 0.305: IC1.3 54.2,45.2 54.75,44.65 57.05,44.65 57.75,45.35 57.75,46.25 57.77,46.27 C45.1
  Top 0.508: 59.86,48.65 C47.1 59.95,48.65 59.59,48.29 C46.1 57.8,48.2 57.85,48.15 57.8,48.1 C45.1
N$58  (via drill 0.8 pad 1.7)
  Top 0.305: v53.55,63.45 52.55,63.45 52.1,62.91 IC2.28
  Top 0.508: R41.1 3.84,62.94 3.86,62.96 | 3.86,62.96 R42.1 | 3.86,62.96 3.86,64.35 v5.25,64.35 | v52.25,77.15 52.25,75.75 54.75,73.25 54.75,70.65 v55.65,69.75
  Bottom 0.508: v5.25,64.35 9.95,64.35 12.05,66.45 12.05,76.45 13.85,78.15 51.25,78.15 v52.25,77.15 | v55.65,69.75 55.65,66.45 53.55,64.45 v53.55,63.45
N$59
  Top 1: L3.2 85.65,51.75 90.78,46.72 X8.5
N$60
  Top 1: X8.3 91.06,41.64 87.65,45.05 84.85,45.05 84.77,45.13 L5.2
N$61  (via drill 0.8 pad 1.7)
  Top 0.305: X7.3 43.23,74.43 43.25,74.45 43.25,72.75 44.05,71.55 45.45,71.55 47.55,69.44 IC2.8 47.55,66.65 49.95,66.65 49.95,65.35 v50.95,64.35 | v49.45,55.85 49.35,55.65 49.05,55.15 49.05,52.85 | 49.05,52.85 49.05,52.75 | 49.05,52.85 49.05,51.05 IC1.12
  Bottom 0.508: v50.95,64.35 50.95,61.35 50.05,60.45 50.05,56.55 v49.45,55.85
N$62  (via drill 0.8 pad 1.7)
  Top 0.305: IC1.14 50.05,52.35 50.05,54.35 51.01,54.99 51.01,56.65 | 38.15,74.35 X7.5 | X7.5 38.05,74.45 | 38.15,74.35 38.15,73.15 41.35,69.95 44.85,69.95 45.6,69.19 IC2.11 45.6,65.85 44.65,65.85 v44.15,65.35 | 38.15,74.35 X7.5 | 51.01,56.65 50.91,56.7 | v45.65,58.05 47.55,58.05 49.51,60.01 IC2.24 49.51,58.09 50.95,56.65 51.01,56.65
  Bottom 0.305: 44.15,65.25 v44.15,65.35
  Bottom 0.508: v45.65,58.05 44.15,59.65 44.15,65.25
N$63
  Top 0.305: 40.65,74.45 X7.4 40.62,74.52 40.65,74.55 40.65,72.95 42.85,70.75 45.15,70.75 46.26,69.64 IC2.10 46.26,64.64 47.45,63.45 48.85,63.45 IC2.23 48.85,60.85 47.65,59.65 44.05,59.65 44.05,54.85 44.55,54.35 44.55,51.7 IC1.16
N$64  (via drill 0.8 pad 1.7)
  Top 0.305: IC1.13 51.95,51.7 51.95,53.25 | X7.1 48.25,74.45 48.25,72.65 48.85,72.05 IC2.6 48.85,67.86 48.85,67.85
  Top 0.508: 51.95,53.25 v51.95,58.05
  Bottom 0.508: v51.95,58.05 51.95,60.15 53.05,61.25 54.45,61.25 61.45,68.25 61.45,76.35 60.75,77.05 56.25,77.05 53.65,74.45 48.25,74.45 X7.1
N$65  (via drill 0.8 pad 1.7)
  Top 0.305: IC2.16 44.3,60.91 43.75,60.35 42.35,60.35
  Top 0.406: v28.75,64.45 30.55,66.45 30.55,73.75
  Top 0.508: 42.35,60.35 40.72,60.35 C55.1 39.8,58.9 38.95,59.75 v38.75,59.75 | 30.55,73.75 v30.15,73.75
  Bottom 0.508: v38.75,59.75 37.45,59.75 30.05,64.45 v28.75,64.45 | v30.15,73.75 30.25,74.75 28.05,76.95 25.15,76.95 24.25,76.05 24.25,75.25 24.23,75.27 SV1.8
N$66  (via drill 0.8 pad 1.7)
  Top 0.305: X7.2 45.7,74.4 45.65,74.35 45.65,72.85 48.2,70.3 IC2.7
  Top 0.508: R43.2 61.85,64.32 v62.65,65.05
  Bottom 0.508: v62.65,65.05 62.65,78.15 55.75,78.15 53.15,75.55 50.85,75.55 49.35,77.15 45.75,77.15 45.65,74.45 45.7,74.4 | 45.7,74.4 45.75,74.35 | X7.2 45.7,74.4
N$67  (via drill 0.8 pad 1.7)
  Top 0.305: IC2.4 50.16,69.06 50.95,69.85 v51.35,69.85
  Top 0.508: SV1.7 24.18,71.32 26.25,69.25 | 26.32,66.98 26.35,66.95 | R47.2 26.32,66.98 | 26.32,66.98 26.25,67.05 26.25,69.25 | 26.25,69.25 v26.05,69.05
  Bottom 0.406: v51.35,69.85 49.85,71.15 29.15,71.15 27.05,69.05 v26.05,69.05
N$68  (via drill 0.8 pad 1.7)
  Top 0.305: IC2.5 49.51,70.11 51.35,71.95 v51.95,71.95
  Top 0.508: SV1.5 21.64,71.06 22.45,70.25 24.15,68.75 24.15,62.15 25.55,60.65 26.35,60.65 26.38,60.62 R48.2
  Bottom 0.305: 21.75,72.75 21.73,72.73 SV1.5
  Bottom 0.406: v51.95,71.95 28.65,71.95 27.45,70.75 22.75,70.75 21.75,71.55 21.75,72.75
N$69
  Top 0.305: IC2.14 41.16,67.97 40.65,67.45 40.6,67.5 C49.2 40.58,67.52 40.55,67.55 40.45,67.45 39.55,67.45 39.15,67.05 39.15,63.15 39.17,63.17 39.2,63.17 | R44.1 39.2,63.17 | 39.2,63.17 39.16,63.24
N$70
  Top 0.305: R44.2 37.32,63.38 37.32,64.18 C48.2
N$71
  Top 0.508: 81.85,74.87 81.85,74.95 84.44,72.36 C63.1 84.45,70.55 81.69,70.55 R51.1
  Top 1.422: Q1.2 81.85,74.87 85.83,74.87
N$72  (via drill 0.8 pad 2)
  Top 0.406: 16.02,16.02 16,16 | 16.02,16.02 R21.2 | 16.5,16.5 16.02,16.02
  Top 0.508: 13.36,16.54 13.35,16.55 13.35,18.25 12.55,19.05 12.85,18.95 v12.9,18.9 | 13.36,16.54 R20.1 | 16.5,16.5 13.4,16.5 13.36,16.54
  Bottom 0.406: X4.2 5.58,16.83
  Bottom 0.508: 5.58,16.83 7.65,18.9 v12.9,18.9
N$73  (via drill 0.8 pad 1.7)
  Top 0.305: IC2.13 44.3,69.15 39.55,69.15 v39.05,69.55
  Top 0.508: v35.45,69.45 33.9,69.4 C50.1 33.95,66.36 C51.1 33.85,63.3 33.85,63.36 R45.1
  Bottom 0.508: v35.45,69.45 39.25,69.45 v39.05,69.55
N$74  (via drill 0.8 pad 1.7)
  Top 0.305: IC3.12 34.35,49.16 34.35,56.45 33.55,57.25 18.25,57.25 16.05,59.45
  Top 0.508: 16.05,59.45 16.05,68.65 v16.65,69.25
  Bottom 0.508: v16.65,69.25 17.75,69.25 19.15,70.65 19.15,72.75 19.13,72.73 SV1.3
N$75  (via drill 0.8 pad 1.7)
  Top 0.305: IC3.10 35.95,47.85 35.95,57.15 34.45,58.65 24.75,58.65 20.45,62.95 20.45,63.55
  Top 0.508: 20.45,63.55 v20.45,68.55
  Bottom 0.508: v20.45,68.55 19.45,67.45 15.65,67.45 14.55,68.55 14.55,74.55 15.25,75.25 16.65,75.25 16.63,75.27 SV1.2
N$76
  Top 0.305: IC3.13 33.55,49.8 33.55,56.05 33.05,56.55 16.75,56.55 13.95,59.35
  Top 0.406: 19.23,75.27 19.25,75.25 | 19.23,75.27 SV1.4 | 19.15,75.35 19.23,75.27
  Top 0.508: 13.95,59.35 13.95,76.25 14.95,77.15 18.45,77.15 19.15,76.45 19.15,75.35
N$77  (via drill 0.8 pad 1.7)
  Top 0.305: IC2.19 46.26,63.34 45.75,63.95 42.85,63.95 v42.25,63.85 | IC1.20 41.9,49.1 41.65,49.35 41.65,50.75 41.25,51.15 40.25,51.15 | 40.25,51.15 40.24,51.16 C54.1 | 40.25,51.15 40.25,52.35 v40.95,53.05
  Top 0.406: 27.37,72.73 29.55,70.55 29.55,67.55 28.65,66.85
  Top 0.508: 27.37,72.73 SV1.9 | v28.85,66.85 28.65,66.85
  Bottom 0.305: 42.15,63.85 v42.25,63.85 42.35,63.85 42.35,63.75
  Bottom 0.508: v40.95,53.05 41.45,53.55 41.45,59.95 39.55,62.25 | v28.85,66.85 30.35,66.85 37.25,62.25 39.55,62.25 | 42.35,63.85 40.65,62.25 39.55,62.25
N$78  (via drill 0.8 pad 1.57, 0.8 pad 1.7)
  Top 0.305: IC3.5 33.3,44.6 33.35,44.6 | 23.05,62.45 23.05,61.55 25.25,59.35 35.15,59.35 35.15,59.25
  Top 0.508: 33.35,44.6 v34.15,44.6 | v37.65,48.85 37.65,49.25 36.95,50.05 36.95,57.45 35.15,59.25 | 23.05,62.45 23.05,65.35 v22.25,66.15
  Bottom 0.508: SV1.6 21.74,76.56 21.05,77.15 14.95,77.15 13.25,75.55 13.25,68.15 15.25,66.15 v22.25,66.15 | v34.15,44.6 34.8,44.6 37.65,47.45 v37.65,48.85
N$79
  Top 0.508: R53.1 | R53.1 73.74,70.96 71.3,73.4 | U$32.2 73.64,69.34 R53.1 | 72.85,74.87 72.85,74.95 71.3,73.4 | C61.1 71.1,73.2 71.3,73.4
  Top 1.422: 71.73,74.87 72.85,74.87 Q1.1
N$80
  Top 0.508: U$26.4 79.31,59.71 80.35,60.75 80.35,61.75 80.38,61.78 C57.1
N$84
  Top 0.508: R50.2 68.8,67.4 68.75,67.35 71.25,64.85 71.85,64.85 72.69,64.01 U$32.4 72.65,63.58 | 72.65,63.58 72.65,63.55 | 72.65,63.58 72.65,63.85 73.75,64.95 75.78,64.95 R53.2 78.54,69.44 | 78.54,69.44 R51.2 | 78.54,69.44 78.55,69.45
N$85
  Top 1: 94.37,28.93 L4.2 94.45,29.05 94.55,29.15 | X8.1 94.14,36.56 94.55,36.35 94.55,29.15 | 94.55,29.15 94.55,28.95
N$86
  Top 0.305: IC2.3 50.8,65.95 54.64,65.97 54.66,65.95
  Top 0.508: 57.35,65.95 C53.1 57.55,66.05 | 57.35,65.95 57.55,66.05 | 57.55,66.05 57.6,66.1 | 54.66,65.95 57.35,65.95 | 63.2,62.4 C52.1 63.3,62.3 63.25,62.25 63.05,62.45 | 57.55,63.15 57.52,63.18 R46.2
  Top 0.61: R46.2 58.62,63.18 59.35,62.45 63.05,62.45
  Top 0.813: 57.55,66.05 57.55,63.15
N$87
  Top 0.508: U$31.4 70.31,43.31 71.25,44.25 71.25,45.75 71.3,45.8 C75.1
N$88
  Top 1: D6.2 86.45,58.9 86.45,56.65 L3.1
N$89
  Top 1: L4.1 94.45,25.05 96.75,22.75 96.75,21.15 96.77,21.13 D7.1
N$90
  Top 0.508: 84.65,41.35 84.65,41.33 L5.1
  Top 1: D5.2 88.05,32.94 88.05,41.35 84.65,41.35
V+
  Top 0.508: D5.1 81.43,33.13 | 81.45,35.45 81.43,35.17 U$27.1 84.55,36.01 | U$27.3 81.71,37.91 82.05,38.25 | 82.05,38.25 83.1,39.3 86.3,39.32 86.3,35.95 84.55,35.95 84.55,36.01 | C65.+ 79.05,45.81 79.05,45.35 78.95,45.25 | 82.05,38.25 81.65,38.35 | C69.2 84.58,35.88 84.65,35.95 84.59,36.01 84.55,36.01
  Top 0.813: 79.05,45.35 80.05,45.35 81.05,44.45 81.05,39.45 81.65,38.35 | C67.2 75.47,45.25 78.95,45.25
  Top 1: 81.43,33.13 81.45,35.45
V-
  Top 0.508: 83.35,22.05 83.16,21.56 83.16,21.54 83.25,21.45 83.3,21.5 C68.1 | 83.3,19.35 83.25,19.35 83.3,19.3 U$29.2
  Top 0.813: 83.35,22.05 83.35,23.25 | C70.1 | C70.1 83.3,19.35 C68.1 | C70.1 83.25,18.55
  Top 1: 83.35,23.25 84.85,24.85 89.45,24.85 93.3,21 D7.2 93.37,20.97 93.35,20.95 93.35,17.95 91.83,16.43 C66.-
VCC
  Top 0.508: 79.63,56.67 U$26.3 80.01,56.19 | 80.15,55.15 80.15,54.45 80.2,54.4 C73.1 80.25,54.35 | 77.01,56.41 U$26.1
  Top 0.813: C71.+ 86,62.2 85.55,61.95 82.85,61.95 82.9,62 | 82.9,62 C72.1 82.9,62 | 82.9,62 82.85,62.05 | D6.1 83.03,61.87 82.9,62
  Top 1: 79.63,56.67 79.65,56.65 81.62,58.92 D6.1
  Top 1.016: 80.15,55.15 80.01,56.19 | 77.01,56.41 76.35,55.55 76.35,52.15 80.25,52.15 80.25,54.35
VDD  (via drill 0.8 pad 1.7)
  Top 0.305: 44.95,48.45 44.95,49.76 IC1.19 IC1.18 IC1.17 44.95,51.05 45.65,51.75 45.65,53.65 | IC1.21 43.25,48.45 44.95,48.45 | IC1.8 44.55,48.45 44.95,48.45 | 45.65,53.65 45.65,55.55 | v46.35,53.65 45.65,53.65
  Top 0.508: 45.56,55.84 45.55,55.85 | 45.56,55.84 C77.1 | 45.65,55.55 45.56,55.84 | 58.35,59.25 60.27,59.27 | 7.44,67.64 7.45,67.65 7.4,67.7 3.9,67.7 3.86,67.74 | 7.44,67.64 R40.2 | 18.92,59.18 18.95,59.15 | 18.92,59.18 R49.2 | v18.15,61.15 18.15,59.95 18.92,59.18 | 3.86,67.74 3.85,67.75 | 3.86,67.74 R42.2 | 7.44,67.64 1.85,67.64 1.85,58.85 v2.85,57.95 | R48.1 26.24,62.66 26.25,62.65 26.26,62.66 R47.1 | R48.1 26.66,62.66 | R45.2 28.88,61.32 v28.65,61.45 27.45,62.65 26.21,62.65 | 26.21,62.65 26.15,62.65 | 26.21,62.65 R48.1 | C58.+ 73.03,60.33 74.59,61.89 U$32.5 | U$26.5 77.41,59.39 76.85,59.95
  Top 0.813: 60.27,59.27 R46.1 | 58.35,59.25 57.9,59.25 v54.15,57.05
  Top 1.016: 58.35,59.25 67.79,59.25 C74.1 72.3,60.6 72.97,59.93 C58.+ 73.03,60.17 | 73.03,60.17 72.85,60.35 | 76.85,59.95 73.25,59.95 73.03,60.17
  Bottom 0.508: v2.85,57.95 3.75,59.05 | 28.65,59.05 v28.65,61.45
  Bottom 0.61: 45.35,52.15 44.35,51.15 40.25,51.15 39.25,52.25 39.25,53.55 40.35,54.95 40.35,57.65 36.95,57.65 | 46.35,52.15 v46.35,53.65 | v18.15,61.15 18.15,61.05 19.95,59.05
  Bottom 0.813: v54.15,57.05 48.65,52.15 46.35,52.15 45.35,52.15
  Bottom 1.016: 36.95,57.65 36.15,58.25 34.95,59.05 28.65,59.05 19.95,59.05 3.75,59.05

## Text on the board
Bottom: Ver1.1 | Shepherdess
